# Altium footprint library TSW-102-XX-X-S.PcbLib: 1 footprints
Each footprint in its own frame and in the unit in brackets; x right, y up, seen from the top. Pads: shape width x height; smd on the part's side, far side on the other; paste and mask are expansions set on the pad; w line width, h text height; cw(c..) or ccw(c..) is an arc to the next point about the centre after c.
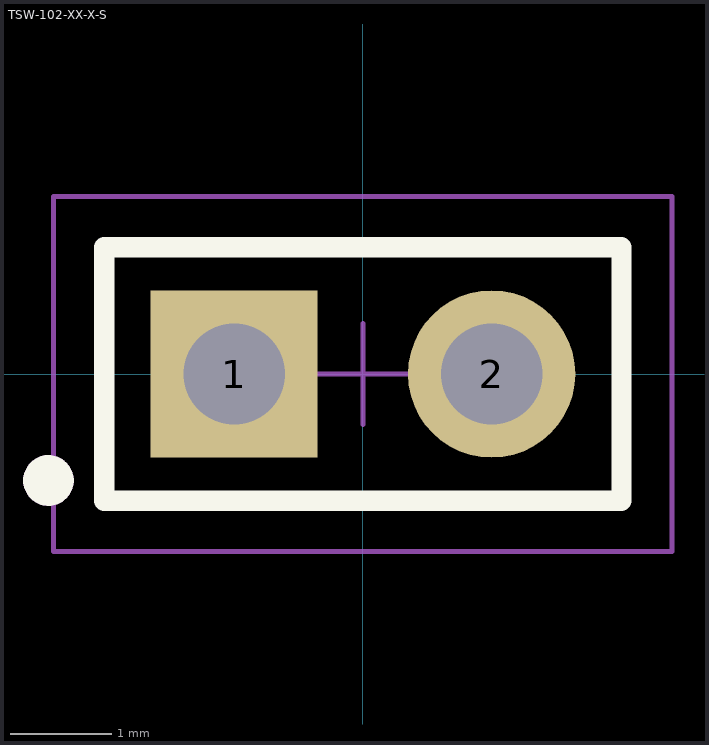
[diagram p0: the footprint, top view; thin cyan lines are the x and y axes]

## TSW-102-XX-X-S [mm] "2.54mm pitch, 2 pin, terminal strip"
height 2.54
pads (2):
  rect 1.65x1.65 hole 1 mask+0: 1(-1.27,0)
  round 1.65 hole 1 mask+0: 2(1.27,0)
Top Overlay:
  circle w0.25: c-3.1,-1.05 r0.125
  lines w0.2: -2.55,-1.25 -2.55,1.25 2.55,1.25 2.55,-1.25 -2.55,-1.25
Mechanical 12:
  lines w0.001: -2.55,-1.25 -2.55,1.25 2.55,1.25 2.55,-1.25 -2.55,-1.25
Mechanical 13:
  circle w0.25: c-3.1,-1.05 r0.125
  lines w0.1: -2.55,-1.25 -2.55,1.25 2.55,1.25 2.55,-1.25 -2.55,-1.25
  text ".Designator" at 0,0 h1.52
Mechanical 15:
  lines w0.05: -0.5,0 0.5,0 ; 0,-0.5 0,0.5 ; -3.05,-1.75 -3.05,1.75 3.05,1.75 3.05,-1.75 -3.05,-1.75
